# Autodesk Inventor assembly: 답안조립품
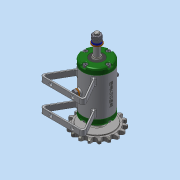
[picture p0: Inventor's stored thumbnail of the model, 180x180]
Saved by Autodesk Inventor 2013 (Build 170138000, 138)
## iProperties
Created: 2016-03
Part Number: 답안조립품
Document SubType Name: Assembly
Designer: Administrator
Author: Administrator
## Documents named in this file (16)
- C:\Users\Administrator\Desktop\460308V1018\답안조립품.iam
- C:\Users\Administrator\Desktop\460308V1018\V벨트풀리.ipt
- C:\Users\Administrator\Desktop\460308V1018\너트 M 8.ipt
- C:\Users\Administrator\Desktop\460308V1018\니플 M 6 x 0.75.ipt
- C:\Users\Administrator\Desktop\460308V1018\베어링 15 x 32 x 9.ipt
- C:\Users\Administrator\Desktop\460308V1018\본체.ipt
- C:\Users\Administrator\Desktop\460308V1018\볼트 M 6 x 8.ipt
- C:\Users\Administrator\Desktop\460308V1018\볼트 M4 x 12.ipt
- C:\Users\Administrator\Desktop\460308V1018\스프로킷.ipt
- C:\Users\Administrator\Desktop\460308V1018\스프링와셔 8.ipt
- C:\Users\Administrator\Desktop\460308V1018\오일 실 15 25 7.ipt
- C:\Users\Administrator\Desktop\460308V1018\와셔 6x11.5.ipt
- C:\Users\Administrator\Desktop\460308V1018\와셔 8x17.ipt
- C:\Users\Administrator\Desktop\460308V1018\축.ipt
- C:\Users\Administrator\Desktop\460308V1018\커버.ipt
- C:\Users\Administrator\Desktop\460308V1018\키 3 x 3 x 12.ipt
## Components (12 placed, 3 different names)
1. V벨트풀리:1
2. KS B 2023 6002 - 15 x 32 x 9:1
3. KS B 2023 6002 - 15 x 32 x 9:2
4. KS B 2023 6002 - 15 x 32 x 9:3
5. ISO 4762 M4 x 12:1
6. ISO 4762 M4 x 12:3
7. ISO 4762 M4 x 12:4
8. ISO 4762 M4 x 12:5
9. ISO 4762 M4 x 12:2
10. ISO 4762 M4 x 12:6
11. ISO 4762 M4 x 12:7
12. ISO 4762 M4 x 12:8
